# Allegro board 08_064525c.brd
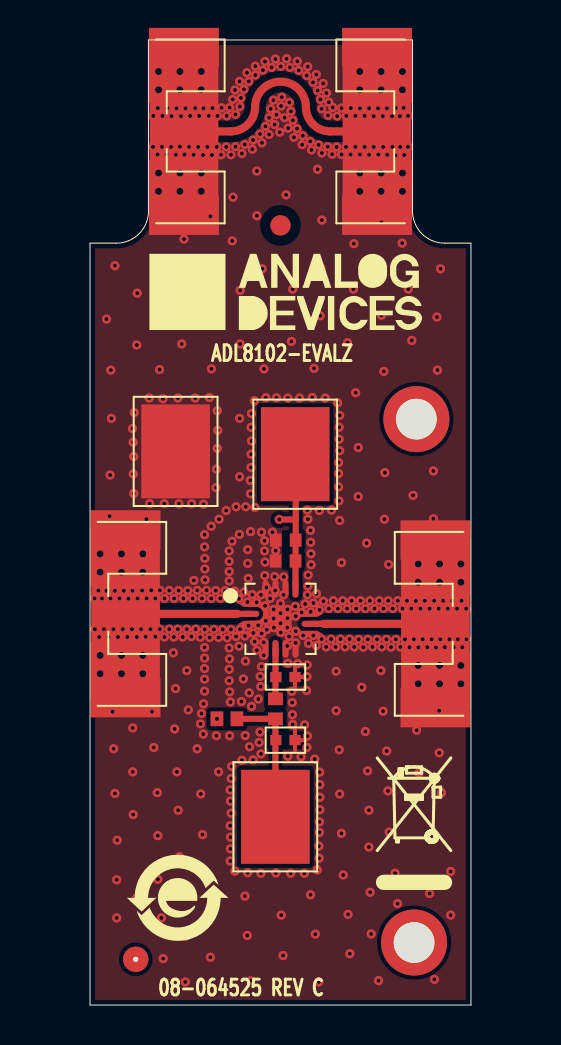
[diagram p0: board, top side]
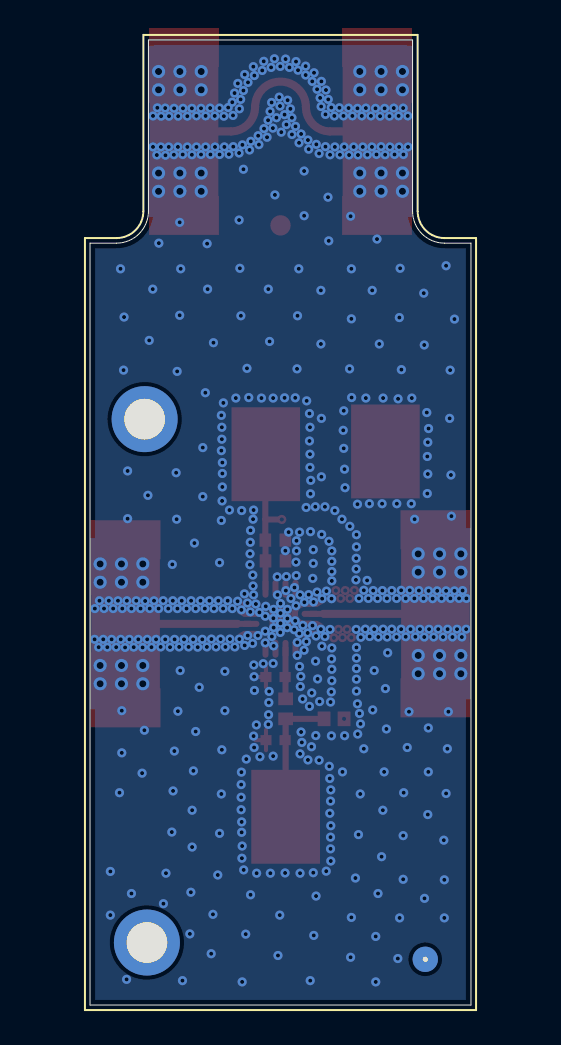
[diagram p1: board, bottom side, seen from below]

Outline 19.05 x 48.26 mm; copper layers: TOP, L2_GND, L3_GND, BOTTOM. Coordinates in mm from the lower left corner of the outline.
Outline path: 0,38.1 0,0 19.05,0 19.05,38.1 17.73,38.1 arc(16.6,38.57) 16.13,39.7 16.13,48.26 2.92,48.26 2.92,39.7 arc(2.45,38.57) 1.32,38.1 0,38.1

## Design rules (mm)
constraint set DEFAULT: min track width 0.203

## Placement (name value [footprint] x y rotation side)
C1  1000pF  [C0402H22]  9.77 16.4 0 top
C2  100pF  [C0402]  9.78 22.21 180 top
C3  1000pF  [C0402H22]  9.77 13.25 0 top
C4  1uF  [C0402]  9.78 23.25 180 top
DUT1  ADL8102ACPZN  [QFN16_3X3_PAD1_1X1_1]  9.53 19.31 270 top
GND  5016  [CNKEY5016TP]  4.28 27.69 90 top
J1  25-146-1000-92  [CNK38G62THK_EDGE]  2.92 43.69 180 top
J2  25-146-1000-92  [CNK38G62THK_EDGE]  16.13 43.69 0 top
NOREF  -  []  22.23 -155.45 0 top
NOREF#2  -  []  189.53 32.97 0 top
NOREF#3  -  []  2.92 48.26 0 top
NOREF#4  -  []  2.92 48.26 270 top
NOREF#5  -  []  0 38.1 0 top
NOREF#6  -  [unnamed#2]  16.32 29.3 0 top
NOREF#7  -  []  0 0 0 top
NOREF#8  -  []  -219.07 -335.79 0 top
NOREF#9  -  []  16.13 48.26 180 top
NOREF#10  -  []  19.05 38.1 180 top
NOREF#11  -  []  -19.88 -45.37 0 top
NOREF#12  -  []  -183.51 -152.91 0 top
NOREF#13  -  []  27.69 22.91 0 top
NOREF#14  -  []  -179.6 -143.31 0 top
NOREF#15  -  []  9.45 66.45 0 top
NOREF#16  -  []  0 38.1 270 top
NOREF#17  -  []  -219.07 -335.79 0 top
NOREF#18  -  []  19.05 0 90 top
NOREF#19  -  []  19.05 0 90 top
NOREF#20  -  []  0 0 0 top
NOREF#21  -  []  3.56 43.69 0 top
NOREF#22  -  []  51.44 27.43 0 top
NOREF#23  -  []  2.29 2.29 0 top
NOREF#24  -  [unnamed#2]  9.53 38.99 0 top
NOREF#25  -  []  0 38.1 0 top
NOREF#26  -  []  19.05 0 0 top
NOREF#27  -  []  0 19.55 0 top
NOREF#28  -  []  9.66 35.66 0 top
NOREF#29  -  []  16 5.82 0 top
NOREF#30  -  []  16.6 38.57 0 top
NOREF#31  -  []  0 0 0 top
NOREF#32  -  [unnamed#2]  16.21 3.12 0 top
NOREF#33  -  []  16.13 48.26 0 top
NOREF#34  -  []  4.38 5.36 0 top
NOREF#35  -  []  2.92 48.26 0 top
NOREF#36  -  [unnamed#2]  2.29 2.29 0 top
NOREF#37  -  []  -219.07 -335.79 0 top
NOREF#38  -  []  2.29 2.29 0 top
NOREF#39  -  []  147.96 38.35 180 bottom
NOREF#40  -  []  9.53 19.05 90 bottom
R1  0  [R0402]  9.27 14.81 90 top
R2  0  [R0402]  6.85 14.31 0 top
RFIN  25-146-1000-92  [CNK38G62THK_EDGE]  0 19.56 180 top
RFOUT  25-146-1000-92  [CNK38G62THK_EDGE]  19.05 19.06 0 top
VBIAS  5016  [CNKEY5016TP]  9.27 9.41 270 top
VDD  5016  [CNKEY5016TP]  10.26 27.55 270 top

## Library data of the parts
C1 C3 = CAP: Tolerance: 10; User Part Number: UPN; alternate symbols: (); part number: CAP_SM-1000PF,50V,10,E033487,C0402H22; tolerance: 10
C2 = CAP: User Part Number: UPN; Tolerance: 5; alternate symbols: (C0402L); part number: CAP_SM-100PF,50V,5,E022402,C0402; tolerance: 5
C4 = CAP: User Part Number: UPN; Tolerance: 10; alternate symbols: (C0402L,C0402L_ALT); part number: CAP_SM-1UF,25V,10,E026618,C0402; tolerance: 10
DUT1 = ADL8102: User Part Number: UPN; Tolerance: N/A; alternate symbols: (); part number: ADL8102_SM-ADL8102ACPZN,E058937,QFN16_3X3_PAD1_1X1_1; tolerance: N/A
GND VBIAS VDD = CNTP1P: Tolerance: N/A; User Part Number: UPN; alternate symbols: (); part number: CNTP1P_SM-5016,E005890,CNKEY5016TP; tolerance: N/A
J1 J2 RFIN RFOUT = CNBNC4P: Tolerance: N/A; User Part Number: UPN; alternate symbols: (CNK38G62THK_EDGE_ADL81XX,CNK38G62THK_EDGE_HMC84X3,CNK40G62THK-SRI-SW_EDGE,CNK38G62THK_EDGE_ADMV1014); part number: CNBNC4P_SM-25-146-1000-92,E023346,CNK38G62THK_EDGE; tolerance: N/A
R1 R2 = RES: User Part Number: UPN; Tolerance: JUMPER; alternate symbols: (R0402L,R0402L_ALT); part number: RES_SM-0,E003438,1/10W,JUMPER,R0402; tolerance: JUMPER

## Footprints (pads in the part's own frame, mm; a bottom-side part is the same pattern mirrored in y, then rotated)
C0402
  rect 0.584x0.66 smd: 1(-0.5,0) 2(0.5,0)
C0402H22
  rect 0.559x0.508 smd: 1(-0.479,0) 2(0.479,0)
CNK38G62THK_EDGE
  custom 0.102x0.102 smd: 1(-1.549,0)
  custom 0.873x0.873 smd: 2(-1.778,-3.302) 3(-1.778,3.302)
  rect 3.429x8.56 smd: 4(-1.778,0)
CNKEY5016TP
  rect 4.699x3.429 smd: 1(0,0)
QFN16_3X3_PAD1_1X1_1
  oval 0.305x0.889 smd: 1(-0.75,-1.5) 2(-0.25,-1.5) 3(0.25,-1.5) 4(0.75,-1.5) 9(0.75,1.5) 10(0.25,1.5) 11(-0.25,1.5) 12(-0.75,1.5)
  oval 0.889x0.305 smd: 5(1.5,-0.75) 6(1.5,-0.25) 7(1.5,0.25) 8(1.5,0.75) 13(-1.5,0.75) 14(-1.5,0.25) 15(-1.5,-0.25) 16(-1.5,-0.75)
  rect 1.092x1.092 smd: PAD(0,0)
R0402
  rect 0.635x0.737 smd: 1(-0.5,0) 2(0.5,0)
unnamed#2
  round 3.302 hole 2.032 unplated: (0,0)

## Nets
GND: C1.2(N2) C2.2(N2) C3.2(N2) C4.2(N2) DUT1.1 DUT1.3 DUT1.4 DUT1.5 DUT1.7 DUT1.8 DUT1.9 DUT1.11 DUT1.12 DUT1.14 DUT1.15 DUT1.16 DUT1.PAD GND.1(N1) J1.2 J1.3 J1.4(SH3) J2.2 J2.3 J2.4(SH3) RFIN.2 RFIN.3 RFIN.4(SH3) RFOUT.2 RFOUT.3 RFOUT.4(SH3)
UNNAMED_3_CAP_I247_N1: C2.1 C4.1 DUT1.13(VDD) R2.1 VDD.1(N1)
UNNAMED_3_CAP_I253_N1: C1.1 DUT1.6 R1.2(N2)
UNNAMED_3_CNBNC4P_I249_CNTR: J1.1 J2.1
UNNAMED_3_CNBNC4P_I251_CNTR: DUT1.2 RFIN.1
UNNAMED_3_CNBNC4P_I252_CNTR: DUT1.10 RFOUT.1
UNNAMED_3_CNTP1P_I226_N1: C3.1 R1.1 R2.2(N2) VBIAS.1(N1)

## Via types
v1: diameter 0.457, hole 0.203, TOP to L3_GND, 2 vias
v2: diameter 0.66, hole 0.356, TOP to BOTTOM, 48 vias
v3: diameter 0.457, hole 0.203, TOP to BOTTOM, 599 vias
v4: diameter 0.457, hole 0.203, TOP to L2_GND, 10 vias

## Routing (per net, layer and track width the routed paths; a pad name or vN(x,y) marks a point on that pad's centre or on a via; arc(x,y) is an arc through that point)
GND: length 5.3
  TOP w0.203: C1.2 10.25,16.91 ; C1.2 10.25,15.89 ; C1.2 10.79,16.4 ; C3.2 10.78,13.25 ; C3.2 10.25,13.75 ; C3.2 10.25,12.74
  TOP w0.305: DUT1.1 8.03,20.06 8.31,20.06 arc(8.67,19.91) 8.81,19.56 arc(8.67,19.21) 8.32,19.06 8.03,19.06 arc(8.03,19.06) DUT1.3
  vias: v2(0.51,22.56) v2(0.51,21.64) v2(0.51,17.48) v2(0.51,16.57) v2(1.57,22.56) v2(1.57,21.64) v2(1.57,17.48) v2(1.57,16.57) v2(2.64,22.56) v2(2.64,21.64) v2(2.64,17.48) v2(2.64,16.57) v2(3.43,46.69) v2(3.43,45.77) v2(3.43,41.61) v2(3.43,40.69) v2(4.49,46.69) v2(4.49,45.77) v2(4.49,41.61) v2(4.49,40.69) v2(5.56,46.69) v2(5.56,45.77) v2(5.56,41.61) v2(5.56,40.69) v2(13.49,46.68) v2(13.49,45.77) v2(13.49,41.61) v2(13.49,40.69) v2(14.56,46.68) v2(14.56,45.77) v2(14.56,41.61) v2(14.56,40.69) v2(15.62,46.68) v2(15.62,45.77) v2(15.62,41.61) v2(15.62,40.69) v2(16.41,22.06) v2(16.41,21.14) v2(16.41,16.98) v2(16.41,16.06) v2(17.48,22.06) v2(17.48,21.14) v2(17.48,16.98) v2(17.48,16.06) v2(18.54,22.06) v2(18.54,21.14) v2(18.54,16.98) v2(18.54,16.06) v3(0.23,20.33) v3(0.24,18.8) v3(0.42,20.73) v3(0.46,18.4) v3(0.6,20.33) v3(0.7,18.8) v3(0.83,34.3) v3(0.83,20.71) v3(0.93,18.4) v3(1,26.5) v3(0.98,24.45) v3(1.03,20.33) v3(1.04,31.75) v3(1.07,29.34) v3(1.13,14.67) v3(1.17,18.8) v3(1.18,12.81) v3(1.24,36.97) v3(1.24,20.71) v3(1.24,10.58) v3(1.33,6.26) v3(1.33,4.36) v3(1.4,18.4) v3(1.36,8.24) v3(1.47,20.33) v3(1.69,20.71) v3(1.64,18.8) v3(1.92,20.32) v3(1.87,18.4) v3(2.12,28.83) v3(2.12,20.71) v3(2.1,18.8) v3(2.13,13.86) v3(2.13,11.66) v3(2.21,29.63) v3(2.16,28.14) v3(2.18,27.43) v3(2.16,26.56) v3(2.18,25.58) v3(2.16,9.53) v3(2.32,5.33) v3(2.36,35.6) v3(2.34,33.01) v3(2.37,20.33) v3(2.34,18.4) v3(2.6,20.73) v3(2.55,18.8) v3(2.82,24.3) v3(2.83,20.33) v3(2.78,18.42) v3(2.96,30.35) v3(2.98,25.07) v3(3.02,18.8) v3(3.06,20.74) v3(3.1,14.67) v3(3.16,44.46) v3(3.15,42.91) v3(3.19,12.88) v3(3.26,20.33) v3(3.26,18.42) v3(3.39,44.86) v3(3.38,42.53) v3(3.37,10.62) v3(3.39,8.47) v3(3.39,6.29) v3(3.48,31.78) v3(3.49,20.74) v3(3.49,18.8) v3(3.62,44.46) v3(3.59,42.91) v3(3.54,36.84) v3(3.58,34.38) v3(3.57,4.36) v3(3.64,30.31) v3(3.71,25.07) v3(3.72,20.33) v3(3.72,18.4) v3(3.66,2.32) v3(3.82,42.53) v3(3.86,44.86) v3(3.96,20.73) v3(3.96,18.8) v3(4.08,44.45) v3(4.05,42.91) v3(4.2,20.33) v3(4.19,18.4) v3(4.17,17.61) v3(4.23,13.8) v3(4.32,44.84) v3(4.29,42.52) v3(4.28,15.82) v3(4.39,30.35) v3(4.43,20.73) v3(4.39,18.8) v3(4.34,11.66) v3(4.41,9.74) v3(4.5,42.93) v3(4.45,25.07) v3(4.47,7.42) v3(4.55,44.45) v3(4.58,33.06) v3(4.64,18.4) v3(4.72,42.53) v3(4.7,38.3) v3(4.67,20.33) v3(4.65,5.58) v3(4.78,44.84) v3(4.76,3.43) v3(4.76,1.16) v3(4.89,20.73) v3(4.84,18.8) v3(4.84,16.73) v3(4.91,14.76) v3(5,44.46) v3(4.95,42.91) v3(4.94,35.74) v3(5.08,25.07) v3(5.13,20.33) v3(5.07,18.43) v3(5.18,42.52) v3(5.19,21.23) v3(5.26,44.86) v3(5.26,30.35) v3(5.28,18.8) v3(5.41,42.91) v3(5.36,20.74) v3(5.36,12.81) v3(5.46,44.46) v3(5.51,18.39) v3(5.52,14.06) v3(5.6,20.33) v3(5.58,14.58) v3(5.54,10.55) v3(5.63,8.52) v3(5.68,44.84) v3(5.65,42.51) v3(5.68,25.04) v3(5.73,23.52) v3(5.73,22.91) v3(5.73,17.88) v3(5.73,17.35) v3(5.73,16.83) v3(5.73,16.29) v3(5.73,15.7) v3(5.68,15.06) v3(5.66,13.55) v3(5.74,22.34) v3(5.74,21.81) v3(5.75,21.26) v3(5.74,18.78) v3(5.78,6.35) v3(5.93,44.46) v3(5.87,42.91) v3(6.02,39.45) v3(5.98,36.82) v3(5.98,34.32) v3(5.97,30.38) v3(5.98,4.38) v3(6.02,2.39) v3(6.12,44.86) v3(6.1,42.51) v3(6.07,31.81) v3(6.06,23.94) v3(6.32,26.8) v3(6.3,25.87) v3(6.32,13.47) v3(6.38,44.46) v3(6.34,42.91) v3(6.36,29.72) v3(6.39,28.74) v3(6.36,27.84) v3(6.43,11.66) v3(6.45,24.3) v3(6.58,44.87) v3(6.55,42.52) v3(6.83,44.46) v3(6.81,42.91) v3(6.81,24.73) v3(6.98,44.88) v3(6.96,22.71) v3(6.96,22.19) v3(6.96,21.68) v3(6.96,21.21) v3(6.97,20.32) v3(6.96,17.86) v3(6.97,17.31) v3(6.96,16.79) v3(6.96,16.22) v3(6.98,15.66) v3(7.02,15.15) v3(6.98,13.46) v3(7.01,10.76) v3(7.02,10.2) v3(7.01,8.97) v3(7.02,8.39) v3(7.02,7.81) v3(7.01,7.2) v3(7.05,42.52) v3(7.11,38.21) v3(7.1,23.19) v3(7.05,18.78) v3(7.09,11.94) v3(7.06,11.33) v3(7.06,9.59) v3(7.14,45.29) v3(7.15,40.4) v3(7.23,20.7) v3(7.25,45.76) v3(7.28,44.54) v3(7.28,42.93) v3(7.3,24.92) v3(7.3,18.43) v3(7.24,6.69) v3(7.48,46.19) v3(7.49,44.93) v3(7.51,35.74) v3(7.51,33.06) v3(7.48,29.34) v3(7.48,26.42) v3(7.47,23.53) v3(7.44,20.32) v3(7.51,18.8) v3(7.45,17.95) v3(7.54,45.36) v3(7.59,42.58) v3(7.57,15.18) v3(7.59,12.24) v3(7.7,45.8) v3(7.73,43.04) v3(7.7,20.65) v3(7.67,16.31) v3(7.79,24.92) v3(7.75,18.45) v3(7.77,17.2) v3(7.76,13.47) v3(7.75,5.45) v3(7.85,46.62) v3(7.89,22.77) v3(7.89,22.09) v3(7.91,21.34) v3(7.87,20.15) v3(7.92,18.97) v3(7.89,6.62) v3(7.86,3.48) v3(7.94,46.19) v3(8.01,26.24) v3(8.03,25.57) v3(8.03,23.67) v3(7.96,15.61) v3(7.98,12.92) v3(8.12,42.8) v3(8.08,29.58) v3(8.05,28.89) v3(8.08,28.21) v3(8.05,27.55) v3(8.05,26.89) v3(8.12,20.52) v3(8.08,14.94) v3(8.04,1.22) v3(8.15,43.26) v3(8.22,30.21) v3(8.17,18.61) v3(8.23,18.17) v3(8.15,12.26) v3(8.27,46.95) v3(8.27,46.51) v3(8.24,24.88) v3(8.33,20.14) v3(8.34,41.71) v3(8.34,39.47) v3(8.41,18.99) v3(8.34,17.74) v3(8.42,15.3) v3(8.5,43.56) v3(8.51,16.43) v3(8.53,15.93) v3(8.5,13.65) v3(8.46,13.13) v3(8.6,43.12) v3(8.61,36.82) v3(8.57,23.65) v3(8.55,20.51) v3(8.59,18.58) v3(8.57,16.93) v3(8.55,12.56) v3(8.55,6.59) v3(8.65,46.75) v3(8.67,34.47) v3(8.7,31.81) v3(8.72,23.22) v3(8.72,22.71) v3(8.69,18.14) v3(8.69,17.49) v3(8.75,47.18) v3(8.78,43.94) v3(8.79,30.37) v3(8.75,22.15) v3(8.74,21.48) v3(8.83,20.88) v3(8.75,19.96) v3(8.79,19.22) v3(8.84,18.77) v3(9.03,44.82) v3(8.95,44.37) v3(8.95,43.54) v3(9,20.33) v3(9.08,46.89) v3(9.12,23.65) v3(9.17,45.25) v3(9.23,44.03) v3(9.23,21.42) v3(9.18,19.79) v3(9.18,19.33) v3(9.19,18.87) v3(9.27,47.31) v3(9.32,44.53) v3(9.32,30.37) v3(9.28,22.72) v3(9.26,20.73) v3(9.3,6.6) v3(9.49,43.65) v3(9.53,20.08) v3(9.53,19.6) v3(9.53,19.09) v3(9.54,46.94) v3(9.59,45.4) v3(9.55,44.96) v3(9.54,18.63) v3(9.56,4.5) v3(9.73,44.37) v3(9.69,21.41) v3(9.68,20.51) v3(9.65,2.48) v3(9.83,47.32) v3(9.8,40.51) v3(9.91,43.85) v3(9.89,30.35) v3(9.87,19.79) v3(9.88,19.34) v3(9.87,18.87) v3(9.87,17.96) v3(9.89,17.08) v3(9.89,12.45) v3(9.99,46.89) v3(9.97,45.14) v3(9.96,18.43) v3(10.03,6.59) v3(10.05,44.69) v3(10.13,35.8) v3(10.07,33.19) v3(10.09,15.68) v3(10.11,15.13) v3(10.12,14.52) v3(10.13,14.03) v3(10.15,44.25) v3(10.2,43.4) v3(10.26,19.94) v3(10.29,19.44) v3(10.29,18.69) v3(10.29,18.11) v3(10.36,47.19) v3(10.35,43.83) v3(10.39,17.07) v3(10.44,46.74) v3(10.48,30.35) v3(10.6,43.03) v3(10.58,19.63) v3(10.55,12.42) v3(10.64,43.47) v3(10.66,18.48) v3(10.73,14.01) v3(10.72,6.59) v3(10.83,46.48) v3(10.76,20.05) v3(10.83,15.73) v3(10.88,46.93) v3(10.87,24.75) v3(10.9,24.3) v3(10.91,21.5) v3(10.9,20.96) v3(10.87,20.51) v3(10.92,18.08) v3(10.86,17.01) v3(10.85,16.42) v3(10.87,13.45) v3(10.85,12.88) v3(11.01,43.19) v3(11.02,23.74) v3(11.02,5.51) v3(11.07,42.76) v3(11.11,30.38) v3(11.04,23.14) v3(11.05,22.57) v3(11.05,22.02) v3(11.04,19.66) v3(11.15,46.14) v3(11.2,31.84) v3(11.18,20.1) v3(11.16,18.48) v3(11.32,46.53) v3(11.33,20.56) v3(11.32,17.98) v3(11.24,12.3) v3(11.26,3.54) v3(11.38,45.73) v3(11.43,43.01) v3(11.38,41.8) v3(11.37,6.76) v3(11.52,45.29) v3(11.51,34.47) v3(11.47,24.73) v3(11.48,19.76) v3(11.48,11.65) v3(11.49,11.02) v3(11.49,10.39) v3(11.49,9.77) v3(11.47,9.16) v3(11.47,8.64) v3(11.44,7.95) v3(11.46,7.34) v3(11.44,1.16) v3(11.58,44.82) v3(11.6,42.61) v3(11.6,39.26) v3(11.56,36.84) v3(11.58,18.3) v3(11.66,46.09) v3(11.67,20.19) v3(11.82,45.61) v3(11.76,30.35) v3(11.81,17.91) v3(11.9,44.49) v3(11.89,42.93) v3(11.94,45.15) v3(11.94,19.82) v3(12.1,42.55) v3(12.08,24.75) v3(12.05,18.3) v3(12.14,44.88) v3(12.17,20.22) v3(12.33,42.91) v3(12.28,17.91) v3(12.31,16.69) v3(12.31,14.72) v3(12.36,44.45) v3(12.38,30.11) v3(12.43,27.13) v3(12.43,26.58) v3(12.43,25.91) v3(12.4,19.82) v3(12.48,29.49) v3(12.46,28.89) v3(12.46,28.3) v3(12.48,27.72) v3(12.45,25.21) v3(12.48,24.23) v3(12.52,18.3) v3(12.46,12.76) v3(12.48,10.55) v3(12.57,44.86) v3(12.57,42.53) v3(12.57,22.12) v3(12.57,8.59) v3(12.64,20.22) v3(12.66,6.5) v3(12.81,44.46) v3(12.8,42.91) v3(12.75,17.91) v3(12.88,33.12) v3(12.85,19.82) v3(12.9,4.53) v3(13.03,42.53) v3(12.98,18.3) v3(12.99,2.57) v3(13.04,44.86) v3(13.08,20.22) v3(13.2,38.07) v3(13.17,35.8) v3(13.21,17.91) v3(13.27,44.46) v3(13.27,42.91) v3(13.28,30.62) v3(13.31,19.82) v3(13.41,27.88) v3(13.41,25.43) v3(13.5,44.84) v3(13.5,42.53) v3(13.53,20.22) v3(13.44,18.29) v3(13.59,15.89) v3(13.73,44.46) v3(13.73,42.91) v3(13.67,17.89) v3(13.83,23.1) v3(13.77,19.82) v3(13.77,13.68) v3(13.89,18.29) v3(13.88,11.71) v3(13.96,44.84) v3(13.96,42.52) v3(14,20.22) v3(13.94,9.74) v3(13.94,7.9) v3(14.01,5.64) v3(14.12,17.91) v3(14.06,3.56) v3(14.19,44.45) v3(14.19,42.91) v3(14.22,19.82) v3(14.4,44.84) v3(14.41,42.53) v3(14.35,18.29) v3(14.43,1.22) v3(14.52,36.82) v3(14.47,20.22) v3(14.57,39.14) v3(14.57,34.49) v3(14.59,17.91) v3(14.54,16.73) v3(14.64,44.45) v3(14.66,42.91) v3(14.69,31.69) v3(14.72,24.3) v3(14.68,19.82) v3(14.66,14.69) v3(14.74,26.62) v3(14.82,18.29) v3(14.83,12.7) v3(14.85,44.84) v3(14.86,42.52) v3(14.94,22.03) v3(14.91,20.22) v3(14.9,10.71) v3(14.96,8.65) v3(15.1,44.45) v3(15.11,42.91) v3(15.05,17.89) v3(15.14,19.82) v3(15.29,44.86) v3(15.28,42.49) v3(15.29,18.29) v3(15.25,6.59) v3(15.39,20.22) v3(15.38,5.07) v3(15.49,44.45) v3(15.51,42.91) v3(15.52,17.91) v3(15.61,38.1) v3(15.62,19.82) v3(15.68,44.87) v3(15.71,42.51) v3(15.75,18.29) v3(15.9,44.46) v3(15.9,42.91) v3(15.91,35.8) v3(15.85,20.22) v3(15.98,17.89) v3(16.09,33.24) v3(16.07,19.82) v3(16.15,25.49) v3(16.19,18.29) v3(16.29,20.21) v3(16.33,13.74) v3(16.42,17.88) v3(16.52,19.82) v3(16.45,11.6) v3(16.64,18.29) v3(16.74,20.22) v3(16.87,17.89) v3(16.98,19.82) v3(16.98,5.58) v3(17.08,18.29) v3(17.17,26.71) v3(17.17,24.32) v3(17.21,20.22) v3(17.22,1.28) v3(17.3,17.88) v3(17.35,34.4) v3(17.37,31.75) v3(17.53,36.82) v3(17.44,19.82) v3(17.51,18.29) v3(17.46,14.72) v3(17.46,12.61) v3(17.58,10.62) v3(17.65,20.22) v3(17.74,17.89) v3(17.89,19.82) v3(17.97,18.29) v3(18.03,6.68) v3(18.03,4.5) v3(18.11,20.22) v3(18.19,17.89) v3(18.35,19.82) v3(18.39,18.29) v3(18.58,20.22) v3(18.62,17.89) v3(18.81,19.82) v3(18.82,18.29) v4(5.83,20.74) v4(5.98,18.38) v4(6.06,20.33) v4(6.2,18.78) v4(6.29,20.73) v4(6.43,18.38) v4(6.52,20.33) v4(6.63,18.78) v4(6.76,20.73) v4(6.86,18.36)
UNNAMED_3_CAP_I247_N1: length 20.1
  TOP w0.305: VDD.1 10.28,27.52 10.28,24.28 ; 10.28,24.28 v1(9.46,24.28) ; 10.28,24.28 C4.1 10.28,23.24 C2.1 10.28,22.21 DUT1.13
  L3_GND w0.305: v1(9.46,24.28) 7.28,24.28 6.34,23.34 6.35,23.33 v1(6.35,14.31)
UNNAMED_3_CAP_I253_N1: length 2.5
  TOP w0.305: DUT1.6 9.28,16.42 C1.1 9.27,16.38 9.27,15.31 R1.2
UNNAMED_3_CNBNC4P_I249_CNTR: length 13
  TOP w0.406: J2.1 12.01,43.69 arc(11.15,44.05) 10.79,44.91 arc(9.53,46.18) 8.26,44.91 arc(7.9,44.05) 7.04,43.69 J1.1
UNNAMED_3_CNBNC4P_I251_CNTR: length 6.5
  TOP w0.305: 7.37,19.56 DUT1.2
  TOP w0.406: RFIN.1 7.37,19.56
UNNAMED_3_CNBNC4P_I252_CNTR: length 6.5
  TOP w0.305: 11.68,19.06 DUT1.10
  TOP w0.406: RFOUT.1 11.68,19.06
UNNAMED_3_CNTP1P_I226_N1: length 6.8
  TOP w0.305: R2.2 7.35,14.31 R1.1 9.27,13.27 C3.1 9.27,13.22 9.27,9.42 VBIAS.1

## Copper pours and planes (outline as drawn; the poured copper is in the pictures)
GND on TOP: 3.17,48.01 15.88,48.01 15.88,47.97 16.13,47.97 16.13,39.41 15.9,39.41 15.9,39.41 16.53,38.29 17.73,37.85 18.8,37.85 18.8,23.34 19.05,23.34 19.05,14.78 18.8,14.78 18.8,0.25 0.25,0.25 0.25,15.28 0,15.28 0,23.84 0.25,23.84 0.25,37.85 1.32,37.85 2.52,38.29 3.15,39.41 2.92,39.41 2.92,47.97 3.17,47.97
GND on BOTTOM, L2_GND, L3_GND: 3.17,48.01 15.88,48.01 15.88,47.97 16.13,47.97 16.13,39.41 15.9,39.41 15.9,39.41 16.53,38.29 17.73,37.85 18.8,37.85 18.8,23.34 19.05,23.34 19.05,14.78 18.8,14.78 18.8,0.25 0.25,0.25 0.25,15.28 0,15.28 0,23.84 0.25,23.84 0.25,37.85 1.32,37.85 2.52,38.29 3.15,39.41 3.15,39.41 2.92,39.41 2.92,47.97 3.17,47.97

Small or netless copper shapes (teardrops, artwork), in the pictures only: 8 on TOP

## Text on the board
User.Comments: 5.    TRIM EDGE PLATING AT CENTER CONDUCTOR IF NOT ALREADY TRIMMED BY PCB MANUFACTURER. | 4.    RoHS COMPLIANCE: ASSEMBLY VENDOR SHOULD ASSURE COMPLIANCE | USE TRIMMING FIXTURE 106356. | 6.    ATTACH TO PCB WITH CENTER PIN ON TOP SIDE TRACE. | WITH LEAD-FREE AND RoHS PCB ASSEMBLY STANDARDS (EU RoHS | DIRECTIVE 2002/95/EC). | MANUALLY DISPENSE SOLDER TO CENTER PIN AND GROUND LEADS, | TOP AND BOTTOM. AFTER REFLOW, SOLDER MUST JOIN CONNECTOR AND PCB EDGE. | SEE NOTE#5 | SEE NOTE#6 | (4 PLACES)
Ref Des/Silkscreen Top: 08-064525 REV C | ADL8102-EVALZ
PAGE_OUTLINE: B | C | ECR - 110354 | ECR - 113182 | 31AUG22 | 14MAR23 | H.NGUYEN | C. NELVIS | CUSTOMER EVALUATION Z
DIMENSION: REMOVE EDGE PLATING | SEE DETAIL A | (4 PLACES) | - | " " | (REF) | (2 PLACES) | SEE NOTE 17
User.15: MUST BE FLAT/FLUSHED. NO BUMPS. | BOARD EDGE IN THE PLATED AND NON-PLATED AREA | EDGE PLATING NOT ALLOWED IN CENTER CONDUCTOR | AND GAP AREA. EDGE PLATING SHOULD BE IN LINE | WITH TOP ETCH. | ROGERS 4350B 10MILS | 2 PLACES | PLATED AREA | 42 MILS +/-4 MILS | NON-PLATED AREAS | SEE NOTE#15 CPWG TRACE SPEC | ROHS COMPLIANCE NOTE:  HOMOGENOUS MATERIALS IN THIS BOARD SHALL BE COMPLIANT | THE EU RoHS DIRECTIVE 2002/95/EC | FLUSH WITHIN .001 SURFACES AFTER FINAL PLATING | 17.    THRU VIAS FILLED WITH NON-CONDUCTIVE EPOXY. | 16.    EDGE PLATING AT CONNECTOR EDGE BUT NOT ALLOWED IN CENTER CONDUCTOR TRACES. | ALL 4 METAL LAYERS MUST CONNECT. ( DETAIL A) | 15.    CRITICAL LINE WIDTH (CPWG) = 16 MILS +/- 1 MIL | CRITICAL LINE GAP (CPWG) = 13 MILS +/- 1 MIL | ADJUST PROCESS TO ACHIEVE CRITICAL WIDTH AND GAPS. | DETAIL A
User.17: L2 GND | 08-      -05
User.18: L3 GND | 08-      -06
User.45: N.NGUYEN | 10/2019 | 10MAR20 | H.N. | FIGURE | SIZE | 8.0 | 14.0 | 10.0 | 80.0 | PLATED | NON-PLATED | DRILL CHART: TOP to L2_GND | ALL UNITS ARE IN MILS | DRILL CHART: TOP to L3_GND | DRILL CHART: TOP to BOTTOM | QTY | 10 | 2 | 599 | 48 | 1 | TOLERANCE/NOTES
